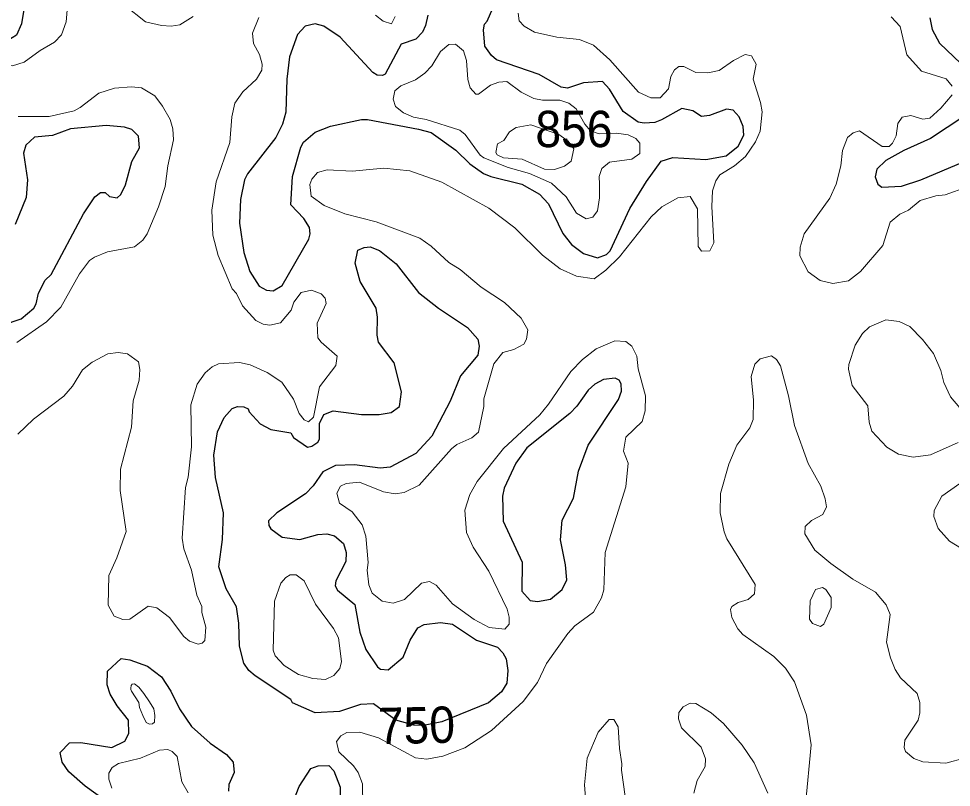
# Model space of a CAD drawing. Extents: x 763.2 to 816.8, y 7896.5 to 7952.7.
# Drawn here: x 774.699 to 778.802, y 7919.324 to 7922.705 of the extents above; entities that cross this region are included whole.
import ezdxf
from ezdxf.enums import TextEntityAlignment as Align

# ---------------------------------------------------------------- set-up
doc = ezdxf.new("R2010")
doc.units = 0
doc.header["$LTSCALE"] = 0.064
doc.layers.add('1', color=7, linetype='Continuous', lineweight=25)
doc.layers.add('2', color=7, linetype='Continuous', lineweight=13)
doc.layers.add('21', color=7, linetype='Continuous')
doc.layers.add('61', color=7, linetype='Continuous')

msp = doc.modelspace()

# ---------------------------------------------------------------- linework, layer by layer
at = {"layer": '1'}
for points in [[(774.7266, 7922.7712), (774.7106, 7922.6816), (774.6893, 7922.6326), (774.651, 7922.6085), (774.6241, 7922.6079), (774.5931, 7922.6195)], [(776.458, 7922.2189), (776.514, 7922.2034), (776.6215, 7922.126), (776.6839, 7922.0663), (776.7432, 7922.0242), (776.7761, 7922.0106), (776.9124, 7921.9764), (776.9899, 7921.933), (777.029, 7921.891), (777.0929, 7921.7602), (777.1302, 7921.711), (777.1831, 7921.6713), (777.2451, 7921.653), (777.2848, 7921.668), (777.3014, 7921.6841), (777.3875, 7921.8696), (777.461, 7921.989), (777.5256, 7922.0782), (777.5765, 7922.0946), (777.7217, 7922.0851), (777.8112, 7922.1017), (777.8639, 7922.144), (777.8882, 7922.1924), (777.8858, 7922.2304), (777.8688, 7922.2722), (777.8425, 7922.3016), (777.8125, 7922.3065), (777.7374, 7922.2789), (777.7026, 7922.274), (777.6644, 7922.2987), (777.616, 7922.3099), (777.5271, 7922.2592), (777.4966, 7922.2484), (777.4508, 7922.2445), (777.424, 7922.2497), (777.3584, 7922.2965), (777.2974, 7922.3949), (777.2671, 7922.4282), (777.1828, 7922.4219), (777.1135, 7922.3993), (777.0848, 7922.4036), (776.988, 7922.4596), (776.8003, 7922.5242), (776.7793, 7922.542), (776.7499, 7922.5836), (776.7435, 7922.6552), (776.7487, 7922.6811), (776.7597, 7922.6939), (776.7841, 7922.7515)], [(776.4986, 7922.7205), (776.4881, 7922.6741), (776.4748, 7922.6454), (776.4457, 7922.6144), (776.3813, 7922.5922), (776.3113, 7922.4606), (776.2989, 7922.4548), (776.2763, 7922.4557), (776.2569, 7922.468), (776.1127, 7922.6235), (776.0415, 7922.6721), (776.0035, 7922.6816), (775.9595, 7922.6714), (775.9258, 7922.635), (775.8896, 7922.537), (775.8779, 7922.4382), (775.8737, 7922.2928), (775.8592, 7922.2401), (775.8306, 7922.1813), (775.7058, 7922.0219), (775.6926, 7921.9962), (775.6747, 7921.9092), (775.6701, 7921.8056), (775.6894, 7921.6757), (775.7155, 7921.593), (775.7572, 7921.528), (775.7896, 7921.51), (775.8184, 7921.5083), (775.8579, 7921.5304), (775.9748, 7921.7343), (775.9818, 7921.7587), (775.9782, 7921.7865), (775.9527, 7921.8252), (775.8966, 7921.8859), (775.9035, 7922.01), (775.9394, 7922.1401), (775.9523, 7922.1614), (776.0037, 7922.2049), (776.0703, 7922.2326), (776.2065, 7922.2608), (776.2337, 7922.2605), (776.458, 7922.2189)], [(778.7072, 7922.7087), (778.7166, 7922.6576), (778.7488, 7922.5975), (778.8435, 7922.507)], [(778.8567, 7922.2741), (778.7097, 7922.1783), (778.5927, 7922.1246), (778.5139, 7922.0804), (778.4734, 7922.0421), (778.4659, 7922.0094), (778.4781, 7921.9765), (778.496, 7921.9635), (778.5829, 7921.9685), (778.6674, 7921.9957), (778.855, 7922.0754)], [(774.6283, 7921.3561), (774.7095, 7921.3846), (774.7655, 7921.432), (774.7763, 7921.4509), (774.7863, 7921.4973), (774.8152, 7921.5551), (774.8421, 7921.5794), (774.9834, 7921.8457), (775.0345, 7921.9207), (775.0585, 7921.9403), (775.0796, 7921.9397), (775.0984, 7921.9225), (775.1325, 7921.9161), (775.1489, 7921.9306), (775.169, 7921.974), (775.196, 7922.0764), (775.2311, 7922.1368), (775.2256, 7922.1873), (775.197, 7922.2176), (775.1645, 7922.2277), (775.0842, 7922.2344), (774.9266, 7922.2196), (774.8483, 7922.1903), (774.7689, 7922.1832), (774.7301, 7922.1488), (774.7203, 7922.1128), (774.7382, 7921.9955), (774.7316, 7921.9174), (774.6839, 7921.7991)], [(776.0219, 7920.9248), (776.0412, 7920.9633), (776.0825, 7920.9798), (776.2066, 7920.9641), (776.284, 7920.9641), (776.3379, 7920.9728), (776.3737, 7920.9986), (776.383, 7921.0634), (776.3504, 7921.1902), (776.2816, 7921.2822), (776.2765, 7921.3127), (776.2779, 7921.3922), (776.2711, 7921.4315), (776.2009, 7921.5493), (776.1797, 7921.6289), (776.1902, 7921.6858), (776.219, 7921.6986), (776.2445, 7921.7018), (776.2862, 7921.6845), (776.3596, 7921.6269), (776.4573, 7921.5), (776.5453, 7921.4313), (776.6734, 7921.3457), (776.718, 7921.2948), (776.7249, 7921.2639), (776.7183, 7921.224), (776.6427, 7921.1342), (776.5966, 7921.0227), (776.5166, 7920.8685), (776.4463, 7920.7922), (776.3323, 7920.7322), (776.2892, 7920.7276), (776.1755, 7920.7423), (776.0921, 7920.7398), (776.0367, 7920.7109), (775.9942, 7920.6493), (775.9609, 7920.6141), (775.8345, 7920.5319), (775.7984, 7920.4964), (775.7999, 7920.4751), (775.8082, 7920.4613), (775.8575, 7920.4247), (775.9362, 7920.4138), (776.0152, 7920.4365), (776.0546, 7920.4381), (776.0884, 7920.4301), (776.1278, 7920.3959), (776.1398, 7920.356), (776.1382, 7920.3167), (776.0943, 7920.2314), (776.0912, 7920.2108), (776.102, 7920.1905), (776.1779, 7920.1286), (776.1995, 7920.0069), (776.2265, 7919.9305), (776.2771, 7919.8531), (776.291, 7919.8429), (776.3239, 7919.8404), (776.3901, 7919.8967), (776.4212, 7919.9715), (776.4541, 7920.0256), (776.4819, 7920.0404), (776.555, 7920.0486), (776.6067, 7920.0419), (776.7121, 7919.9715), (776.8045, 7919.9396), (776.8285, 7919.9156), (776.8433, 7919.8887), (776.8499, 7919.8375), (776.8468, 7919.7822), (776.8225, 7919.7435), (776.7655, 7919.696), (776.561, 7919.6112), (776.48, 7919.5956), (776.437, 7919.5976), (776.3576, 7919.6195), (776.26, 7919.6904), (776.2018, 7919.6886), (776.1105, 7919.6578), (776.0032, 7919.6511), (775.9036, 7919.6954), (775.8961, 7919.7102), (775.7385, 7919.8142), (775.7113, 7919.8384), (775.6892, 7919.8698), (775.6701, 7919.9454), (775.6666, 7920.0455), (775.6568, 7920.1181), (775.6118, 7920.1967), (775.5797, 7920.2942), (775.5962, 7920.4136), (775.5992, 7920.5309), (775.565, 7920.6873), (775.5569, 7920.785), (775.574, 7920.8881)], [(775.574, 7920.8881), (775.6024, 7920.9507), (775.638, 7920.9906), (775.6618, 7920.9985), (775.6889, 7920.9969), (775.7087, 7920.9886)], [(775.7087, 7920.9886), (775.713, 7920.976), (775.7617, 7920.9219), (775.8085, 7920.8981), (775.896, 7920.8837), (775.9077, 7920.863), (775.9694, 7920.8204), (775.9884, 7920.8241), (776.0147, 7920.8425), (776.0216, 7920.8549), (776.0219, 7920.9248)], [(775.0899, 7919.8353), (775.1493, 7919.8904), (775.1876, 7919.8842), (775.265, 7919.8567), (775.327, 7919.8098), (775.3679, 7919.7473), (775.4067, 7919.6698), (775.4586, 7919.5918), (775.5408, 7919.5175), (775.6129, 7919.4679), (775.6424, 7919.4338), (775.6466, 7919.3891), (775.6229, 7919.3367), (775.6212, 7919.3071)], [(775.1834, 7919.5599), (775.1819, 7919.6192), (775.1327, 7919.6823), (775.1018, 7919.7341), (775.0884, 7919.7744), (775.0899, 7919.8353)], [(775.1219, 7919.2355), (774.9914, 7919.3284), (774.9196, 7919.3925), (774.89, 7919.4351), (774.8814, 7919.4767), (774.9226, 7919.5193), (774.972, 7919.5205), (775.1089, 7919.4983), (775.1658, 7919.527), (775.1834, 7919.5599)], [(775.8902, 7919.2189), (775.9333, 7919.3279), (775.9842, 7919.4065), (776.0168, 7919.4177), (776.0631, 7919.4192), (776.0858, 7919.396), (776.1138, 7919.3239), (776.1135, 7919.2082)]]:
    msp.add_lwpolyline(points, dxfattribs=at)
msp.add_lwpolyline([(777.0897, 7920.1941), (777.1096, 7920.2361), (777.1048, 7920.3027), (777.0818, 7920.4119), (777.0895, 7920.4985), (777.1391, 7920.5961), (777.1609, 7920.7151), (777.2034, 7920.8293), (777.3375, 7921.0296), (777.3511, 7921.0668), (777.3495, 7921.0981), (777.3405, 7921.114), (777.3233, 7921.1233), (777.2715, 7921.117), (777.2333, 7921.0976), (777.2034, 7921.0709), (777.1544, 7921.001), (777.1228, 7920.9675), (776.9344, 7920.8167), (776.8858, 7920.7498), (776.8348, 7920.6403), (776.827, 7920.6051), (776.8308, 7920.4943), (776.9138, 7920.314), (776.9128, 7920.1871), (776.9482, 7920.1462), (776.9808, 7920.1409), (777.039, 7920.151)], close=True, dxfattribs=at)
at = {"layer": '2'}
for points in [[(774.4572, 7922.7063), (774.5164, 7922.5912), (774.558, 7922.5414), (774.6087, 7922.5043), (774.6723, 7922.4976), (774.7233, 7922.5141), (774.7929, 7922.5645), (774.8568, 7922.6012), (774.8873, 7922.6341), (774.9076, 7922.6904), (774.9139, 7922.7594)], [(775.165, 7922.7643), (775.2567, 7922.6911), (775.3274, 7922.6747), (775.3702, 7922.6717), (775.4074, 7922.678), (775.4662, 7922.7142)], [(775.7555, 7922.7094), (775.7277, 7922.6404), (775.7324, 7922.5951), (775.7588, 7922.5478), (775.7699, 7922.5039), (775.7683, 7922.4778), (775.7449, 7922.4379), (775.6844, 7922.3835), (775.6502, 7922.3324), (775.636, 7922.2728), (775.6271, 7922.1599), (775.5675, 7921.9864), (775.5484, 7921.8625), (775.5535, 7921.753), (775.5759, 7921.6624), (775.6375, 7921.5167), (775.6564, 7921.4952), (775.6828, 7921.4413), (775.742, 7921.3772), (775.7741, 7921.3603), (775.8041, 7921.3571), (775.8503, 7921.3669), (775.8978, 7921.422), (775.909, 7921.458), (775.9417, 7921.5001), (775.9863, 7921.5112), (776.0302, 7921.4946), (776.0477, 7921.4751), (776.0511, 7921.4514), (776.0121, 7921.3658), (776.0153, 7921.3014), (776.0289, 7921.2815), (776.1001, 7921.2203), (776.0941, 7921.1793), (776.022, 7921.0854), (775.9955, 7920.952), (775.9733, 7920.9316), (775.9549, 7920.9396), (775.9332, 7920.9678), (775.9075, 7921.0312), (775.8569, 7921.1057), (775.7926, 7921.1486), (775.7176, 7921.1822), (775.67, 7921.1925), (775.5781, 7921.1858), (775.5496, 7921.1738), (775.5194, 7921.147), (775.4838, 7921.0975), (775.4565, 7921.0061), (775.4595, 7920.8214), (775.4447, 7920.688), (775.4334, 7920.6427), (775.4185, 7920.4202), (775.4251, 7920.3732), (775.4596, 7920.2797), (775.4832, 7920.1691), (775.5053, 7920.1189), (775.5048, 7920.0926), (775.5218, 7920.0289), (775.5185, 7919.9701), (775.5054, 7919.9586), (775.4882, 7919.954), (775.45, 7919.9664), (775.4248, 7919.9869), (775.3622, 7920.0706), (775.3073, 7920.114), (775.2678, 7920.1204), (775.1874, 7920.0642), (775.1566, 7920.0619), (775.1196, 7920.0765), (775.0919, 7920.1253), (775.0951, 7920.2551), (775.1309, 7920.3331), (775.172, 7920.4489), (775.1454, 7920.6291), (775.1475, 7920.7235), (775.1949, 7920.9075), (775.2019, 7921.024), (775.2293, 7921.1147), (775.2312, 7921.1613), (775.2253, 7921.1952), (775.1779, 7921.2301), (775.1368, 7921.2368), (775.0917, 7921.2301), (775.0226, 7921.1942), (774.9799, 7921.1596), (774.935, 7921.0885), (774.8976, 7921.0447), (774.764, 7920.9427), (774.6946, 7920.8774)], [(776.1652, 7920.5363), (776.1107, 7920.5733), (776.0991, 7920.6177), (776.1144, 7920.6486), (776.1391, 7920.6601), (776.198, 7920.6666), (776.3038, 7920.6242), (776.3551, 7920.6142), (776.3947, 7920.62), (776.46, 7920.6528), (776.6028, 7920.812), (776.6266, 7920.831), (776.6922, 7920.8606), (776.7213, 7920.8867), (776.7444, 7920.9982), (776.745, 7921.033), (776.7885, 7921.1864), (776.829, 7921.2367), (776.8773, 7921.2501), (776.9209, 7921.2736), (776.9332, 7921.2946), (776.9386, 7921.3363), (776.9089, 7921.3877), (776.8362, 7921.4559), (776.7339, 7921.5242), (776.6413, 7921.6017), (776.5914, 7921.632), (776.5131, 7921.7036), (776.4636, 7921.7397), (776.2715, 7921.8105), (776.1335, 7921.8468), (776.0421, 7921.8827), (775.9861, 7921.9237), (775.9791, 7921.9752), (775.9891, 7921.9993), (776.0135, 7922.0288), (776.0565, 7922.0403), (776.1663, 7922.0341), (776.3051, 7922.047), (776.4201, 7922.0354), (776.5608, 7921.9863), (776.7672, 7921.8717), (776.8812, 7921.7842), (777.0024, 7921.664), (777.0802, 7921.6051), (777.1528, 7921.5727), (777.23, 7921.5608), (777.2818, 7921.5979), (777.3425, 7921.6571), (777.4812, 7921.8334), (777.5287, 7921.8778), (777.5988, 7921.917), (777.6522, 7921.9221), (777.6847, 7921.8688), (777.6884, 7921.7028), (777.7022, 7921.6824), (777.7385, 7921.6838), (777.7572, 7921.7184), (777.7474, 7921.8786), (777.7508, 7921.9468), (777.7649, 7921.9915), (777.7835, 7922.0176), (777.8471, 7922.0579), (777.8956, 7922.0987), (777.9404, 7922.1625), (777.9608, 7922.2099), (777.9693, 7922.2946), (777.9624, 7922.3354), (777.93, 7922.439), (777.9428, 7922.504), (777.9225, 7922.5405), (777.8952, 7922.5466), (777.8439, 7922.5212), (777.7809, 7922.4763), (777.7305, 7922.4663), (777.677, 7922.4672), (777.6241, 7922.4947), (777.6022, 7922.4937), (777.5834, 7922.4796), (777.5675, 7922.4497), (777.557, 7922.3968), (777.5212, 7922.3564), (777.4793, 7922.3566), (777.4249, 7922.3814), (777.2997, 7922.5243), (777.2271, 7922.588), (777.1655, 7922.6124), (777.0655, 7922.6227), (776.9677, 7922.6457), (776.9223, 7922.672), (776.9002, 7922.6945), (776.8962, 7922.7286)], [(776.355, 7922.7148), (776.3385, 7922.682), (776.3022, 7922.6941), (776.268, 7922.72)], [(778.5369, 7922.7134), (778.5758, 7922.6703), (778.6054, 7922.5452), (778.67, 7922.4742), (778.7791, 7922.4396), (778.8054, 7922.4085)], [(774.6914, 7921.2804), (774.822, 7921.3718), (774.8839, 7921.4352), (774.9667, 7921.582), (775.0111, 7921.6411), (775.033, 7921.6562), (775.0902, 7921.6786), (775.2084, 7921.7016), (775.2449, 7921.7306), (775.2641, 7921.7581), (775.3143, 7921.877), (775.3427, 7921.966), (775.3543, 7922.0571), (775.3804, 7922.1712), (775.3773, 7922.2204), (775.3648, 7922.2611), (775.3322, 7922.3203), (775.2979, 7922.3646), (775.2396, 7922.4001), (775.1957, 7922.4055), (775.1211, 7922.3988), (775.0516, 7922.3771), (774.9701, 7922.3142), (774.9427, 7922.3), (774.8337, 7922.274), (774.6971, 7922.2739)], [(778.8055, 7922.3694), (778.7559, 7922.3112), (778.7065, 7922.2671), (778.6755, 7922.2623), (778.6235, 7922.2788), (778.5851, 7922.2718), (778.5663, 7922.244), (778.5585, 7922.1889), (778.5426, 7922.1573), (778.5277, 7922.1427), (778.4971, 7922.1428), (778.3979, 7922.2112), (778.3703, 7922.2032), (778.3453, 7922.1827), (778.3227, 7922.1251), (778.3158, 7922.058), (778.2946, 7921.9765), (778.2669, 7921.9152), (778.1545, 7921.7585), (778.1368, 7921.6997), (778.1352, 7921.6617), (778.172, 7921.5917), (778.2249, 7921.5524), (778.2796, 7921.5398), (778.3492, 7921.5521), (778.4015, 7921.592), (778.4999, 7921.7077), (778.5321, 7921.8097), (778.5752, 7921.8452), (778.6136, 7921.8628), (778.6637, 7921.9052), (778.7335, 7921.9254), (778.7739, 7921.9292), (778.872, 7921.9647)], [(778.572, 7921.3731), (778.5141, 7921.3795), (778.4413, 7921.3498), (778.411, 7921.3201), (778.3792, 7921.2679), (778.3504, 7921.1837), (778.3492, 7921.1636), (778.3659, 7921.091), (778.4349, 7921.0015), (778.4396, 7920.9298), (778.4515, 7920.8906), (778.5179, 7920.8202), (778.5697, 7920.7898), (778.6342, 7920.7753), (778.7105, 7920.786), (778.8314, 7920.8405)], [(778.7679, 7921.1045), (778.7549, 7921.1574), (778.7228, 7921.232), (778.6748, 7921.294), (778.6183, 7921.3503), (778.572, 7921.3731)], [(776.2123, 7919.244), (776.2109, 7919.3391), (776.1926, 7919.3897), (776.1721, 7919.4183), (776.107, 7919.4798), (776.0973, 7919.5247), (776.116, 7919.551), (776.1429, 7919.5651), (776.1997, 7919.5671), (776.2814, 7919.5409), (776.4451, 7919.4542), (776.4944, 7919.4473), (776.564, 7919.4604), (776.662, 7919.4979), (776.7788, 7919.5733), (776.9177, 7919.7008), (776.9817, 7919.7853), (777.0207, 7919.869), (777.1147, 7920.0011), (777.1459, 7920.0339), (777.2269, 7920.0939), (777.2633, 7920.1567), (777.2724, 7920.1924), (777.279, 7920.356), (777.3694, 7920.646), (777.3793, 7920.7503), (777.3598, 7920.8025), (777.3699, 7920.864), (777.441, 7920.9323), (777.4547, 7920.9805), (777.4564, 7921.0457), (777.4236, 7921.1647), (777.4183, 7921.2209), (777.3958, 7921.2643), (777.3704, 7921.2852), (777.3207, 7921.2878), (777.2385, 7921.252), (777.1793, 7921.2061), (777.1274, 7921.1525), (777.03, 7921.0089), (776.9918, 7920.9629), (776.8318, 7920.8146), (776.7153, 7920.6683), (776.6833, 7920.6112), (776.6611, 7920.5428), (776.6693, 7920.4449), (776.6986, 7920.3797), (776.7677, 7920.2739), (776.848, 7920.1068), (776.8565, 7920.0728), (776.8565, 7920.0419), (776.837, 7920.0198), (776.7692, 7920.0269), (776.7027, 7920.0615), (776.6069, 7920.131), (776.5348, 7920.2125), (776.5063, 7920.2293), (776.4715, 7920.222), (776.3955, 7920.1504), (776.3465, 7920.1342), (776.2973, 7920.1428), (776.254, 7920.1781), (776.2389, 7920.2141)], [(778.8636, 7919.4534), (778.7769, 7919.4296), (778.6767, 7919.4362), (778.6364, 7919.4506), (778.6004, 7919.4819), (778.5938, 7919.4996), (778.5971, 7919.5315), (778.6554, 7919.6186), (778.663, 7919.6516), (778.6629, 7919.6965), (778.6508, 7919.7363), (778.5774, 7919.8056), (778.5546, 7919.8427), (778.5341, 7919.8936), (778.5165, 7919.9623), (778.5328, 7920.084), (778.5147, 7920.1259), (778.4674, 7920.1828), (778.368, 7920.2398), (778.2721, 7920.3079), (778.201, 7920.3674), (778.1567, 7920.4383), (778.1586, 7920.4714), (778.1858, 7920.4976), (778.2357, 7920.5245), (778.2518, 7920.5575), (778.2469, 7920.5927), (778.2274, 7920.648), (778.1711, 7920.7479), (778.1121, 7920.9155), (778.0857, 7921.0463), (778.0493, 7921.1784), (778.032, 7921.2051), (778.0101, 7921.2217), (777.9602, 7921.2084), (777.9365, 7921.1844), (777.9216, 7921.131), (777.9313, 7921.0266), (777.9295, 7920.9413), (777.9145, 7920.9044), (777.8584, 7920.8281), (777.8225, 7920.7459), (777.7868, 7920.6157), (777.7852, 7920.5309), (777.8016, 7920.4482), (777.8142, 7920.4165), (777.9379, 7920.2153), (777.9363, 7920.1755)], [(778.8392, 7920.9923), (778.7975, 7921.0408), (778.7679, 7921.1045)], [(778.8384, 7920.6601), (778.7591, 7920.6052), (778.7254, 7920.5417), (778.7252, 7920.5145), (778.7443, 7920.4625), (778.7936, 7920.4062), (778.8731, 7920.3578)], [(776.2389, 7920.2141), (776.2322, 7920.2791), (776.2369, 7920.312), (776.2254, 7920.4283), (776.21, 7920.4788), (776.1652, 7920.5363)], [(777.9363, 7920.1755), (777.9071, 7920.1501), (777.8637, 7920.1371), (777.8364, 7920.1192), (777.8297, 7920.1054), (777.8361, 7920.0702)], [(777.8361, 7920.0702), (777.862, 7920.0214), (777.8845, 7919.9954), (778.0201, 7919.8991), (778.0727, 7919.8482), (778.1111, 7919.7876), (778.165, 7919.6415), (778.1844, 7919.5114), (778.1599, 7919.2466)], [(777.9937, 7919.2977), (777.9335, 7919.4311), (777.8818, 7919.5094), (777.7998, 7919.6051), (777.7456, 7919.651), (777.6772, 7919.6926), (777.6521, 7919.6936), (777.6216, 7919.6778), (777.6029, 7919.6524), (777.6011, 7919.6244), (777.6145, 7919.5856), (777.7009, 7919.4998), (777.7208, 7919.4496), (777.719, 7919.4156), (777.6839, 7919.3546), (777.6685, 7919.2977)], [(777.3673, 7919.2835), (777.3506, 7919.3988), (777.3527, 7919.4266), (777.3415, 7919.4949), (777.3362, 7919.5901), (777.3163, 7919.6226), (777.2966, 7919.6216), (777.248, 7919.5664), (777.1991, 7919.452), (777.1885, 7919.3355), (777.1955, 7919.2404)], [(775.1086, 7919.3205), (775.0949, 7919.3602), (775.0951, 7919.3858), (775.1103, 7919.4108), (775.1382, 7919.4293), (775.2348, 7919.4517), (775.3183, 7919.4866), (775.3544, 7919.4899), (775.3747, 7919.4812), (775.3968, 7919.4601), (775.4169, 7919.3477), (775.4442, 7919.2998)]]:
    msp.add_lwpolyline(points, dxfattribs=at)
for points in [[(776.6856, 7922.4007), (776.6747, 7922.4376), (776.6688, 7922.521), (776.6554, 7922.5629), (776.6208, 7922.5925), (776.5911, 7922.5911), (776.5542, 7922.5599), (776.5156, 7922.497), (776.4862, 7922.4656), (776.4445, 7922.436), (776.3806, 7922.409), (776.353, 7922.3866), (776.3456, 7922.3508), (776.3567, 7922.3185), (776.3912, 7922.2899), (776.4353, 7922.2709), (776.4917, 7922.2607), (776.6391, 7922.2149), (776.6633, 7922.1958), (776.729, 7922.1043), (776.7451, 7922.0922), (776.8523, 7922.0504), (776.9459, 7922.0239), (777.0432, 7921.9817), (777.1075, 7921.9211), (777.1522, 7921.8487), (777.1954, 7921.8241), (777.2249, 7921.8321), (777.2447, 7921.8599), (777.2542, 7921.916), (777.2543, 7921.9769), (777.2522, 7922.0098), (777.2641, 7922.0455), (777.2979, 7922.0732), (777.3954, 7922.0868), (777.4317, 7922.112), (777.4312, 7922.1573), (777.413, 7922.1775), (777.3805, 7922.1944), (777.3293, 7922.2016), (777.2523, 7922.1984), (777.2145, 7922.212), (777.189, 7922.2404), (777.1508, 7922.3084), (777.1188, 7922.3329), (777.0787, 7922.3462), (777.0025, 7922.3463), (776.9644, 7922.3531), (776.9093, 7922.3808), (776.8469, 7922.4284), (776.8106, 7922.4251), (776.7745, 7922.4117), (776.7218, 7922.3728), (776.7105, 7922.3728)], [(777.075, 7922.195), (777.1159, 7922.1657), (777.1413, 7922.1322), (777.1291, 7922.0782), (777.0994, 7922.0565), (777.0552, 7922.0412), (777.012, 7922.0433), (776.914, 7922.0863), (776.831, 7922.0931), (776.803, 7922.1064), (776.7979, 7922.1167), (776.8054, 7922.1548), (776.8332, 7922.1691), (776.8575, 7922.2076), (776.8868, 7922.2264), (776.9518, 7922.2376)], [(776.1053, 7919.981), (776.0843, 7920.0219), (776.0041, 7920.1288), (775.9551, 7920.2317), (775.9202, 7920.259), (775.8925, 7920.258), (775.8734, 7920.2472), (775.8525, 7920.2212), (775.8246, 7920.1428), (775.8179, 7919.9274), (775.827, 7919.9015), (775.8667, 7919.8594), (775.9291, 7919.8207), (775.9935, 7919.8027), (776.0481, 7919.7975), (776.0852, 7919.8161), (776.1119, 7919.8467), (776.1187, 7919.8777)], [(778.1913, 7920.0437), (778.1781, 7920.0628), (778.1799, 7920.1435), (778.2042, 7920.1945), (778.235, 7920.2031), (778.2492, 7920.1941), (778.2728, 7920.1592), (778.2728, 7920.1147), (778.2408, 7920.0415), (778.2254, 7920.0309)], [(775.2077, 7919.7787), (775.1988, 7919.7782), (775.1937, 7919.7713), (775.1928, 7919.7606), (775.1925, 7919.7547), (775.1953, 7919.7464), (775.2273, 7919.6969), (775.2297, 7919.6746), (775.2446, 7919.6395), (775.2598, 7919.6083), (775.2747, 7919.6021), (775.2874, 7919.6034), (775.2969, 7919.6109), (775.2982, 7919.6395), (775.2934, 7919.6684), (775.2744, 7919.7004), (775.2493, 7919.7361), (775.2273, 7919.7638)]]:
    msp.add_lwpolyline(points, close=True, dxfattribs=at)

# ---------------------------------------------------------------- texts
at = {"layer": '21', "width": 0.95}
msp.add_text('856', height=0.16, dxfattribs=at).set_placement((776.9718, 7922.1396))
at = {"layer": '61', "width": 0.95}
msp.add_text('750', height=0.16, rotation=1.246, dxfattribs=at).set_placement((776.4504, 7919.5168), align=Align.CENTER)

doc.saveas('drawing.dxf')
